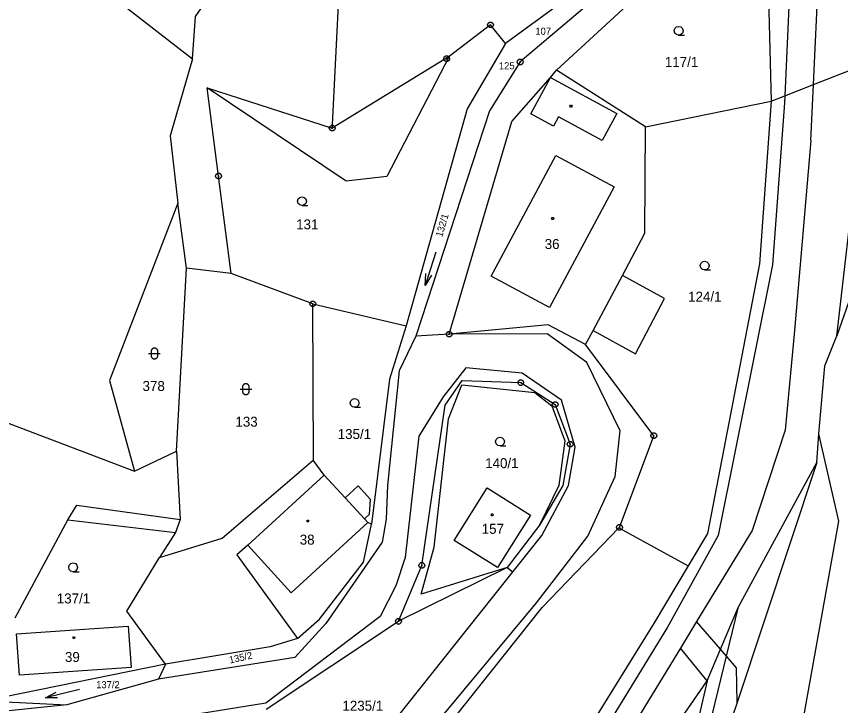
# Model space of a CAD drawing. Extents: x -694465 to -690527, y -983694 to -978978.
# Drawn here: x -691879.9 to -691739.5, y -981514.6 to -981397.2 of the extents above; entities that cross this region are included whole.
import ezdxf

# ---------------------------------------------------------------- set-up
doc = ezdxf.new("R2010")
doc.units = 0
for name, color, linetype in [('Vrstva 1', 7, 'Continuous'), ('Vrstva 18', 7, 'Continuous'), ('Vrstva 19', 7, 'Continuous'), ('Vrstva 24', 7, 'Continuous'), ('Vrstva 25', 7, 'Continuous')]:
    doc.layers.add(name, color=color, linetype=linetype)

msp = doc.modelspace()

# ---------------------------------------------------------------- linework, layer by layer
at = {"layer": 'Vrstva 1'}
for p, q in [((-691796.33, -981491.03), (-691795.344, -981491.788)), ((-691837.34, -981515.16), (-691814.83, -981500.21))]:
    msp.add_line(p, q, dxfattribs=at)
for points in [[(-691744.14, -981408.83), (-691741.58, -981353.92)], [(-691900.63, -981365.11), (-691849.91, -981404.43)], [(-691826.081, -981415.657), (-691824.37, -981381.54)], [(-691772.54, -981386.67), (-691794.11, -981404.98)], [(-691787.92, -981406.39), (-691766.86, -981386.95)], [(-691751.97, -981387.5), (-691751.37, -981411.65)], [(-691849.42, -981397.25), (-691843.31, -981388.41)], [(-691747.99, -981387.86), (-691749.01, -981410.73)], [(-691785.64, -981393.78), (-691796.61, -981401.86)], [(-691849.91, -981404.43), (-691849.42, -981397.25)], [(-691799.17, -981398.65), (-691806.171, -981404.072)], [(-691796.61, -981401.86), (-691799.17, -981398.65)], [(-691796.61, -981401.86), (-691803.14, -981412.95)], [(-691806.171, -981404.072), (-691826.11, -981416.24)], [(-691806.171, -981404.072), (-691816.8, -981424.47)], [(-691849.91, -981404.43), (-691853.69, -981417.58)], [(-691794.11, -981404.98), (-691799.31, -981413.3)], [(-691788.95, -981407.63), (-691787.92, -981406.39)], [(-691772.77, -981416.03), (-691787.92, -981406.39)], [(-691744.14, -981408.83), (-691736.87, -981405.98)], [(-691795.54, -981415.09), (-691788.95, -981407.63)], [(-691792.31, -981413.83), (-691788.95, -981407.63)], [(-691788.95, -981407.63), (-691777.62, -981413.76)], [(-691823.75, -981425.3), (-691847.4, -981409.4)], [(-691847.4, -981409.4), (-691826.11, -981416.24)], [(-691845.47, -981424.4), (-691847.4, -981409.4)], [(-691749.01, -981410.73), (-691744.14, -981408.83)], [(-691744.59, -981418.37), (-691744.14, -981408.83)], [(-691751.37, -981411.65), (-691749.01, -981410.73)], [(-691749.01, -981410.73), (-691749.06, -981411.94)], [(-691772.77, -981416.03), (-691751.37, -981411.65)], [(-691751.37, -981411.65), (-691753.34, -981439.34)], [(-691749.06, -981411.94), (-691751.1, -981439.54)], [(-691803.14, -981412.95), (-691813.5, -981449.91)], [(-691799.31, -981413.3), (-691811.9, -981451.66)], [(-691788.44, -981415.92), (-691792.31, -981413.83)], [(-691777.62, -981413.76), (-691780.11, -981418.37)], [(-691806.2, -981451.33), (-691795.54, -981415.09)], [(-691787.58, -981414.33), (-691788.44, -981415.92)], [(-691780.11, -981418.37), (-691787.58, -981414.33)], [(-691826.11, -981416.24), (-691826.081, -981415.657)], [(-691772.86, -981434.1), (-691772.77, -981416.03)], [(-691853.69, -981417.58), (-691852.4, -981429.02)], [(-691744.59, -981418.37), (-691747.39, -981450.72)], [(-691799.06, -981441.43), (-691788.04, -981420.9)], [(-691788.04, -981420.9), (-691778.1, -981426.24)], [(-691740.16, -981451.62), (-691736.7, -981421.66)], [(-691843.33, -981441.01), (-691845.47, -981424.4)], [(-691816.8, -981424.47), (-691823.75, -981425.3)], [(-691778.1, -981426.24), (-691789.11, -981446.76)], [(-691731.67, -981427.26), (-691740.16, -981451.62)], [(-691852.4, -981429.02), (-691864.07, -981459.19)], [(-691850.92, -981440.07), (-691852.4, -981429.02)], [(-691776.691, -981441.313), (-691772.86, -981434.1)], [(-691753.34, -981439.34), (-691762.19, -981485.27)], [(-691852.64, -981471.24), (-691850.92, -981440.07)], [(-691843.33, -981441.01), (-691850.92, -981440.07)], [(-691751.1, -981439.54), (-691760.37, -981485.59)], [(-691829.43, -981446.16), (-691843.33, -981441.01)], [(-691789.11, -981446.76), (-691799.06, -981441.43)], [(-691781.667, -981450.685), (-691776.691, -981441.313)], [(-691781.667, -981450.685), (-691774.47, -981454.692), (-691769.53, -981445.244), (-691776.691, -981441.313)], [(-691829.33, -981472.8), (-691829.43, -981446.16)], [(-691829.43, -981446.16), (-691813.5, -981449.91)], [(-691813.5, -981449.91), (-691816.34, -981458.97)], [(-691789.31, -981449.71), (-691806.2, -981451.33)], [(-691782.95, -981453.1), (-691789.31, -981449.71)], [(-691782.95, -981453.1), (-691781.667, -981450.685)], [(-691811.9, -981451.66), (-691814.69, -981457.59)], [(-691806.2, -981451.33), (-691811.9, -981451.66)], [(-691789.53, -981451.29), (-691806.2, -981451.33)], [(-691782.75, -981456.17), (-691789.53, -981451.29)], [(-691747.39, -981450.72), (-691748.94, -981467.68)], [(-691742.23, -981456.73), (-691740.16, -981451.62)], [(-691771.35, -981468.61), (-691782.95, -981453.1)], [(-691777.06, -981467.77), (-691782.75, -981456.17)], [(-691814.69, -981457.59), (-691816.71, -981477.08)], [(-691803.37, -981457.08), (-691807.21, -981462.02)], [(-691793.77, -981457.99), (-691803.37, -981457.08)], [(-691743.21, -981468.29), (-691742.23, -981456.73)], [(-691816.34, -981458.97), (-691819.4, -981483.66)], [(-691787.06, -981462.54), (-691793.77, -981457.99)], [(-691864.07, -981459.19), (-691859.79, -981474.68)], [(-691796.33, -981491.03), (-691814.83, -981500.21), (-691810.86, -981490.7), (-691806.9, -981463.4), (-691803.96, -981459.2), (-691794.01, -981459.57), (-691788.14, -981463.3), (-691785.59, -981470.06)], [(-691806.3, -981465.72), (-691804.03, -981459.95)], [(-691804.03, -981459.95), (-691791.59, -981461.26)], [(-691894.02, -981461.68), (-691859.79, -981474.68)], [(-691791.59, -981461.26), (-691788.7, -981463.53)], [(-691807.21, -981462.02), (-691811.34, -981468.71)], [(-691784.72, -981470.55), (-691787.06, -981462.54)], [(-691788.7, -981463.53), (-691786.51, -981469.46)], [(-691808.74, -981487.6), (-691806.3, -981465.72)], [(-691811.34, -981468.71), (-691813.68, -981489.33)], [(-691777.93, -981475.56), (-691777.06, -981467.77)], [(-691777.2, -981484.22), (-691771.35, -981468.61)], [(-691748.94, -981467.68), (-691754.59, -981484.76)], [(-691743.57, -981473.15), (-691743.21, -981468.29)], [(-691739.83, -981483.15), (-691743.21, -981468.29)], [(-691785.59, -981470.06), (-691786.83, -981477.12), (-691790.82, -981483.86)], [(-691786.51, -981469.46), (-691787.51, -981477.11)], [(-691859.79, -981474.68), (-691852.64, -981471.24)], [(-691852.64, -981471.24), (-691852.02, -981482.86)], [(-691785.86, -981477.09), (-691784.72, -981470.55)], [(-691844.84, -981486.08), (-691829.332, -981472.802)], [(-691829.332, -981472.802), (-691829.33, -981472.8)], [(-691827.46, -981475.32), (-691829.332, -981472.802)], [(-691743.57, -981473.15), (-691757.157, -981514.06)], [(-691756.89, -981497.77), (-691743.57, -981473.15)], [(-691827.46, -981475.32), (-691840.5, -981487.27)], [(-691823.91, -981479.19), (-691827.46, -981475.32)], [(-691782.56, -981485.74), (-691777.93, -981475.56)], [(-691821.7, -981477.17), (-691823.91, -981479.19)], [(-691819.61, -981479.45), (-691821.7, -981477.17)], [(-691816.71, -981477.08), (-691816.91, -981482.85)], [(-691787.51, -981477.11), (-691790.82, -981483.86)], [(-691790.41, -981485.59), (-691785.86, -981477.09)], [(-691792.36, -981482.12), (-691797.99, -981491.08), (-691805.35, -981486.47), (-691799.72, -981477.5), (-691792.36, -981482.12)], [(-691823.91, -981479.19), (-691820.64, -981482.76)], [(-691819.76, -981481.95), (-691819.61, -981479.45)], [(-691871.15, -981482.96), (-691869.63, -981480.45)], [(-691869.63, -981480.45), (-691852.02, -981482.86)], [(-691880.14, -981499.65), (-691871.15, -981482.96)], [(-691871.15, -981482.96), (-691852.79, -981485.12)], [(-691852.02, -981482.86), (-691852.79, -981485.12)], [(-691820.64, -981482.76), (-691819.76, -981481.95)], [(-691820.05, -981483.41), (-691820.64, -981482.76)], [(-691816.91, -981482.85), (-691817.59, -981486.72)], [(-691820.05, -981483.41), (-691833.09, -981495.36)], [(-691820.79, -981490.12), (-691819.4, -981483.66)], [(-691819.4, -981483.66), (-691820.05, -981483.41)], [(-691790.82, -981483.86), (-691796.33, -981491.03)], [(-691790.33, -981497.88), (-691777.28, -981484.303)], [(-691777.28, -981484.303), (-691777.2, -981484.22)], [(-691777.28, -981484.303), (-691765.493, -981490.797)], [(-691745.78, -981516.44), (-691739.83, -981483.15)], [(-691852.79, -981485.12), (-691855.51, -981489.37)], [(-691829.98, -981535.3), (-691790.41, -981485.59)], [(-691791.3, -981497.07), (-691782.56, -981485.74)], [(-691760.37, -981485.59), (-691769.03, -981501.19)], [(-691762.19, -981485.27), (-691765.493, -981490.797)], [(-691754.59, -981484.76), (-691764.046, -981500.238)], [(-691855.51, -981489.37), (-691844.84, -981486.08)], [(-691817.59, -981486.72), (-691827.21, -981500.62)], [(-691840.5, -981487.27), (-691842.37, -981488.88)], [(-691833.09, -981495.36), (-691840.5, -981487.27)], [(-691810.97, -981495.61), (-691808.74, -981487.6)], [(-691861.12, -981498.49), (-691855.51, -981489.37)], [(-691842.37, -981488.88), (-691832.02, -981503.15)], [(-691813.68, -981489.33), (-691815.28, -981494.15)], [(-691828.27, -981499.84), (-691820.79, -981490.12)], [(-691796.33, -981491.03), (-691810.97, -981495.61)], [(-691765.493, -981490.797), (-691771.29, -981500.5)], [(-691815.28, -981494.15), (-691817.95, -981499.41)], [(-691824.06, -981536.48), (-691791.3, -981497.07)], [(-691821.73, -981537.34), (-691790.33, -981497.88)], [(-691759.975, -981504.99), (-691756.89, -981497.77)], [(-691758.956, -981506.179), (-691756.89, -981497.77)], [(-691854.51, -981507.49), (-691861.12, -981498.49)], [(-691817.95, -981499.41), (-691837.44, -981514.14)], [(-691860.84, -981501.03), (-691860.34, -981508.07), (-691879.38, -981509.41), (-691879.87, -981502.37), (-691860.84, -981501.03)], [(-691827.21, -981500.62), (-691832.48, -981506.4)], [(-691832.02, -981503.15), (-691828.27, -981499.84)], [(-691769.03, -981501.19), (-691799.62, -981551.16)], [(-691771.29, -981500.5), (-691792.15, -981534.17)], [(-691764.046, -981500.238), (-691766.818, -981504.776)], [(-691759.975, -981504.99), (-691764.046, -981500.238)], [(-691832.02, -981503.15), (-691836.69, -981504.57)], [(-691836.69, -981504.57), (-691854.51, -981507.49)], [(-691766.818, -981504.776), (-691794.83, -981550.63)], [(-691762.27, -981510.36), (-691766.818, -981504.776)], [(-691762.27, -981510.36), (-691759.975, -981504.99)], [(-691758.956, -981506.179), (-691759.975, -981504.99)], [(-691832.48, -981506.4), (-691855.71, -981510.07)], [(-691761.37, -981516), (-691758.956, -981506.179)], [(-691757.157, -981514.06), (-691757.275, -981508.142), (-691758.956, -981506.179)], [(-691854.51, -981507.49), (-691885.25, -981513.76)], [(-691854.51, -981507.49), (-691855.71, -981510.07)], [(-691855.71, -981510.07), (-691871.29, -981514.43)], [(-691802.41, -981568.49), (-691762.27, -981510.36)], [(-691762.27, -981510.36), (-691766.03, -981526.78)], [(-691885.25, -981513.76), (-691871.29, -981514.43)], [(-691871.29, -981514.43), (-691903.711, -981517.765)], [(-691837.44, -981514.14), (-691853.33, -981516.71)], [(-691757.157, -981514.06), (-691758.03, -981516.69)]]:
    msp.add_lwpolyline(points, dxfattribs=at)
at = {"layer": 'Vrstva 24'}
for points in [[(-691799.016, -981398.174), (-691798.766, -981398.356), (-691798.67, -981398.65), (-691798.766, -981398.944), (-691799.016, -981399.126), (-691799.324, -981399.126), (-691799.574, -981398.944), (-691799.67, -981398.65), (-691799.574, -981398.356), (-691799.324, -981398.174)], [(-691806.466, -981403.944), (-691806.216, -981404.126), (-691806.12, -981404.42), (-691806.216, -981404.714), (-691806.466, -981404.896), (-691806.774, -981404.896), (-691807.024, -981404.714), (-691807.12, -981404.42), (-691807.024, -981404.126), (-691806.774, -981403.944)], [(-691793.956, -981404.504), (-691793.706, -981404.686), (-691793.61, -981404.98), (-691793.706, -981405.274), (-691793.956, -981405.456), (-691794.264, -981405.456), (-691794.514, -981405.274), (-691794.61, -981404.98), (-691794.514, -981404.686), (-691794.264, -981404.504)], [(-691825.956, -981415.764), (-691825.706, -981415.946), (-691825.61, -981416.24), (-691825.706, -981416.534), (-691825.956, -981416.716), (-691826.264, -981416.716), (-691826.514, -981416.534), (-691826.61, -981416.24), (-691826.514, -981415.946), (-691826.264, -981415.764)], [(-691845.316, -981423.924), (-691845.066, -981424.106), (-691844.97, -981424.4), (-691845.066, -981424.694), (-691845.316, -981424.876), (-691845.624, -981424.876), (-691845.874, -981424.694), (-691845.97, -981424.4), (-691845.874, -981424.106), (-691845.624, -981423.924)], [(-691829.276, -981445.684), (-691829.026, -981445.866), (-691828.93, -981446.16), (-691829.026, -981446.454), (-691829.276, -981446.636), (-691829.584, -981446.636), (-691829.834, -981446.454), (-691829.93, -981446.16), (-691829.834, -981445.866), (-691829.584, -981445.684)], [(-691806.046, -981450.854), (-691805.796, -981451.036), (-691805.7, -981451.33), (-691805.796, -981451.624), (-691806.046, -981451.806), (-691806.354, -981451.806), (-691806.604, -981451.624), (-691806.7, -981451.33), (-691806.604, -981451.036), (-691806.354, -981450.854)], [(-691793.856, -981459.094), (-691793.606, -981459.276), (-691793.51, -981459.57), (-691793.606, -981459.864), (-691793.856, -981460.046), (-691794.164, -981460.046), (-691794.414, -981459.864), (-691794.51, -981459.57), (-691794.414, -981459.276), (-691794.164, -981459.094)], [(-691787.986, -981462.824), (-691787.736, -981463.006), (-691787.64, -981463.3), (-691787.736, -981463.594), (-691787.986, -981463.776), (-691788.294, -981463.776), (-691788.544, -981463.594), (-691788.64, -981463.3), (-691788.544, -981463.006), (-691788.294, -981462.824)], [(-691771.196, -981468.134), (-691770.946, -981468.316), (-691770.85, -981468.61), (-691770.946, -981468.904), (-691771.196, -981469.086), (-691771.504, -981469.086), (-691771.754, -981468.904), (-691771.85, -981468.61), (-691771.754, -981468.316), (-691771.504, -981468.134)], [(-691785.436, -981469.584), (-691785.186, -981469.766), (-691785.09, -981470.06), (-691785.186, -981470.354), (-691785.436, -981470.536), (-691785.744, -981470.536), (-691785.994, -981470.354), (-691786.09, -981470.06), (-691785.994, -981469.766), (-691785.744, -981469.584)], [(-691777.046, -981483.744), (-691776.796, -981483.926), (-691776.7, -981484.22), (-691776.796, -981484.514), (-691777.046, -981484.696), (-691777.354, -981484.696), (-691777.604, -981484.514), (-691777.7, -981484.22), (-691777.604, -981483.926), (-691777.354, -981483.744)], [(-691810.706, -981490.224), (-691810.456, -981490.406), (-691810.36, -981490.7), (-691810.456, -981490.994), (-691810.706, -981491.176), (-691811.014, -981491.176), (-691811.264, -981490.994), (-691811.36, -981490.7), (-691811.264, -981490.406), (-691811.014, -981490.224)], [(-691814.676, -981499.734), (-691814.426, -981499.916), (-691814.33, -981500.21), (-691814.426, -981500.504), (-691814.676, -981500.686), (-691814.984, -981500.686), (-691815.234, -981500.504), (-691815.33, -981500.21), (-691815.234, -981499.916), (-691814.984, -981499.734)]]:
    msp.add_lwpolyline(points, close=True, dxfattribs=at)
for points in [[(-691799.289, -981398.65), (-691799.05, -981398.65)], [(-691806.739, -981404.42), (-691806.5, -981404.42)], [(-691794.229, -981404.98), (-691793.99, -981404.98)], [(-691826.229, -981416.24), (-691825.99, -981416.24)], [(-691845.589, -981424.4), (-691845.35, -981424.4)], [(-691829.549, -981446.16), (-691829.31, -981446.16)], [(-691806.319, -981451.33), (-691806.08, -981451.33)], [(-691794.129, -981459.57), (-691793.89, -981459.57)], [(-691788.259, -981463.3), (-691788.02, -981463.3)], [(-691771.469, -981468.61), (-691771.23, -981468.61)], [(-691785.709, -981470.06), (-691785.47, -981470.06)], [(-691777.319, -981484.22), (-691777.08, -981484.22)], [(-691810.979, -981490.7), (-691810.74, -981490.7)], [(-691814.949, -981500.21), (-691814.71, -981500.21)]]:
    msp.add_lwpolyline(points, dxfattribs=at)
at = {"layer": 'Vrstva 25'}
for points in [[(-691767.11, -981400.42), (-691767.485, -981400.319), (-691767.759, -981400.045), (-691767.86, -981399.67), (-691767.759, -981399.295), (-691767.485, -981399.021), (-691767.11, -981398.92), (-691766.735, -981399.021), (-691766.461, -981399.295), (-691766.36, -981399.67), (-691766.461, -981400.045), (-691766.735, -981400.319), (-691767.11, -981400.42), (-691766.11, -981400.421)], [(-691831.25, -981429.43), (-691831.625, -981429.329), (-691831.899, -981429.055), (-691832, -981428.68), (-691831.899, -981428.305), (-691831.625, -981428.031), (-691831.25, -981427.93), (-691830.875, -981428.031), (-691830.601, -981428.305), (-691830.5, -981428.68), (-691830.601, -981429.055), (-691830.875, -981429.329), (-691831.25, -981429.43), (-691830.25, -981429.431)], [(-691808.449, -981437.338), (-691810.311, -981443.042)], [(-691762.69, -981440.39), (-691763.065, -981440.289), (-691763.339, -981440.015), (-691763.44, -981439.64), (-691763.339, -981439.265), (-691763.065, -981438.991), (-691762.69, -981438.89), (-691762.315, -981438.991), (-691762.041, -981439.265), (-691761.94, -981439.64), (-691762.041, -981440.015), (-691762.315, -981440.289), (-691762.69, -981440.39), (-691761.69, -981440.391)], [(-691809.215, -981441.296), (-691810.311, -981443.042), (-691810.166, -981440.986)], [(-691857.4, -981454.6), (-691855.4, -981454.6)], [(-691841.82, -981460.68), (-691839.82, -981460.68)], [(-691822.31, -981463.78), (-691822.685, -981463.679), (-691822.959, -981463.405), (-691823.06, -981463.03), (-691822.959, -981462.655), (-691822.685, -981462.381), (-691822.31, -981462.28), (-691821.935, -981462.381), (-691821.661, -981462.655), (-691821.56, -981463.03), (-691821.661, -981463.405), (-691821.935, -981463.679), (-691822.31, -981463.78), (-691821.31, -981463.781)], [(-691797.53, -981470.36), (-691797.905, -981470.259), (-691798.179, -981469.985), (-691798.28, -981469.61), (-691798.179, -981469.235), (-691797.905, -981468.961), (-691797.53, -981468.86), (-691797.155, -981468.961), (-691796.881, -981469.235), (-691796.78, -981469.61), (-691796.881, -981469.985), (-691797.155, -981470.259), (-691797.53, -981470.36), (-691796.53, -981470.361)], [(-691870.24, -981491.78), (-691870.615, -981491.679), (-691870.889, -981491.405), (-691870.99, -981491.03), (-691870.889, -981490.655), (-691870.615, -981490.381), (-691870.24, -981490.28), (-691869.865, -981490.381), (-691869.591, -981490.655), (-691869.49, -981491.03), (-691869.591, -981491.405), (-691869.865, -981491.679), (-691870.24, -981491.78), (-691869.24, -981491.781)], [(-691869.134, -981511.844), (-691874.966, -981513.256)], [(-691872.904, -981513.271), (-691874.966, -981513.256), (-691873.14, -981512.299)]]:
    msp.add_lwpolyline(points, dxfattribs=at)
for points in [[(-691785.353, -981412.348), (-691785.265, -981412.5), (-691785.353, -981412.652), (-691785.527, -981412.652), (-691785.615, -981412.5), (-691785.527, -981412.348)], [(-691788.483, -981431.478), (-691788.395, -981431.63), (-691788.483, -981431.782), (-691788.657, -981431.782), (-691788.745, -981431.63), (-691788.657, -981431.478)], [(-691856.9, -981454.1), (-691856.805, -981453.806), (-691856.555, -981453.624), (-691856.245, -981453.624), (-691855.995, -981453.806), (-691855.9, -981454.1), (-691855.9, -981455.1), (-691855.995, -981455.394), (-691856.245, -981455.576), (-691856.555, -981455.576), (-691856.805, -981455.394), (-691856.9, -981455.1)], [(-691841.32, -981460.18), (-691841.225, -981459.886), (-691840.975, -981459.704), (-691840.665, -981459.704), (-691840.415, -981459.886), (-691840.32, -981460.18), (-691840.32, -981461.18), (-691840.415, -981461.474), (-691840.665, -981461.656), (-691840.975, -981461.656), (-691841.225, -981461.474), (-691841.32, -981461.18)], [(-691830.183, -981482.988), (-691830.095, -981483.14), (-691830.183, -981483.292), (-691830.357, -981483.292), (-691830.445, -981483.14), (-691830.357, -981482.988)], [(-691798.763, -981481.938), (-691798.675, -981482.09), (-691798.763, -981482.242), (-691798.937, -981482.242), (-691799.025, -981482.09), (-691798.937, -981481.938)], [(-691870.013, -981502.868), (-691869.925, -981503.02), (-691870.013, -981503.172), (-691870.187, -981503.172), (-691870.275, -981503.02), (-691870.187, -981502.868)]]:
    msp.add_lwpolyline(points, close=True, dxfattribs=at)

# ---------------------------------------------------------------- texts
at = {"layer": 'Vrstva 18'}
for s, height, p in [('107', 1.2, (-691791.523, -981400.34)), ('117/1', 1.7, (-691769.459, -981405.82)), ('125', 1.2, (-691797.723, -981406.22)), ('131', 1.7, (-691832.255, -981433.48)), ('124/1', 1.7, (-691765.501, -981445.79)), ('378', 1.7, (-691858.421, -981461)), ('133', 1.7, (-691842.6, -981467.08)), ('135/1', 1.7, (-691825.181, -981469.18)), ('140/1', 1.7, (-691800.064, -981474.14)), ('137/1', 1.7, (-691873.024, -981497.18)), ('137/2', 1.2, (-691866.323, -981511.61)), ('1235/1', 1.7, (-691824.377, -981515.44))]:
    msp.add_text(s, height=height, dxfattribs=at).set_placement(p)
for s, rotation, p in [('132/1', 73.79696, (-691807.383, -981434.874)), ('135/2', 12.60507, (-691843.539, -981507.42))]:
    msp.add_text(s, height=1.2, rotation=rotation, dxfattribs=at).set_placement(p)
at = {"layer": 'Vrstva 19'}
for s, p in [('36', (-691789.922, -981436.83)), ('157', (-691800.653, -981485.32)), ('38', (-691831.642, -981487.16)), ('39', (-691871.632, -981507.14))]:
    msp.add_text(s, height=1.7, dxfattribs=at).set_placement(p)

doc.saveas('drawing.dxf')
